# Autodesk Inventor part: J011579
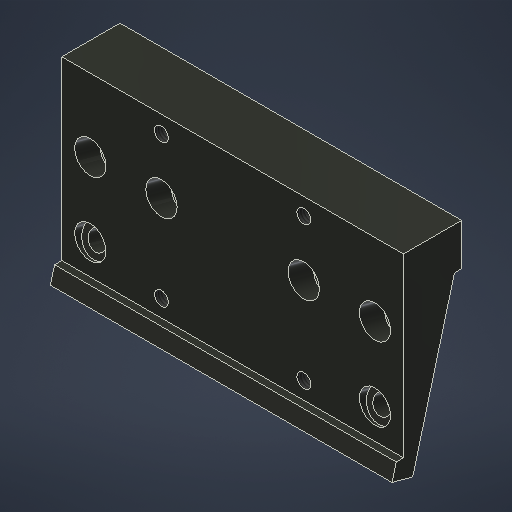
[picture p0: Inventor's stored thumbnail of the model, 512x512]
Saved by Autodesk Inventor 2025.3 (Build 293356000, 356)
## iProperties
RuleStatus: InUse
Created: 2026-02
Project: COMMON
Material: ALUMINUM, 6061-T651
Catalog Web Link: https://www.janelia.org/
Vendor: HHMI: JRC - JET
Document SubType Name: Modeling
Designer: sohna
Density: 2.7 g/cm^3
Appearance: RAL6015_Black_olive
Part Number: J011579
Description: VENT ROTATION TO GONIO BRKT
AfterDocSave0: file://Part Number Cleaner
LAB/DEPT: COMMON
REQUESTING SCIENTIST: COMMON
SURFACE ROUGHNESS: 63 Ra
DESIGN DEPARTMENT: HHMI: JRC - ID&F
SPECIAL FINISH: ANODIZE PER MIL-A-8625F, TYPE II, CLASS 2 (BLACK)
ALTERED ITEM PART NUMBER: N/A
ALTERED ITEM VENDOR: N/A
ALTERED ITEM DESCRIPTION: N/A
Title: Standard
Author: sohna
Revision Number: -
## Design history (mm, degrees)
sketch "Sketch1"
  geometry: L1 (0, 28.727)-(0, -62.166) reference; L2 (-106.448, 0)-(90.075, 0) reference; L3 (62, 0)-(0, 0); L4 (47.197, -17.904)-(-78.373, 15.742); L5 (47.197, -17.904)-(49.933, -49.181); L6 (-5.499, 4.013)-(-7.448, -3.262); L7 (-7.448, -3.262)-(47.197, -17.904); L8 (47.197, -17.904)-(47.419, -20.444); L9 (62, 0)-(62, -20.444); L10 (62, -20.444)-(47.419, -20.444); L11 (0, 0)-(0, 2.54); L12 (0, 2.54)-(-5.499, 4.013)
  constraints: 20 end point, 4 point on line, 2 perpendicular, 1 horizontal, 1 parallel, 1 vertical
  dimensions: "d0" = 17.90446 distance from line of L4.start L2; "d1" = 14.80312 horizontal distance of L4.start L3.start; "d2" = 62 distance from line of L1 L3.start; "d3" = 15 deg angle of L4 L3; "d4" = 110 deg angle of L5 L4; "d5" = 130 distance of L4.start L4.end; "d6" = 2.54 distance from line of L10 L4.start; "d7" = 2.54 distance from line of L2 L11.end; "d8" = 6.35 distance from line of L6 L3.end
extrude "Extrusion1" new body sketch "Sketch1" stored distance "d9" = 120; taper "d10" = 0 deg
sketch "Sketch2"
  geometry: L1 (60, 75.89)-(60, -21.338) reference; L2 (-24, 0)-(144, 0) reference; L3 (35, 56)-(85, 56); L4 (85, 56)-(85, 6); L5 (85, 6)-(35, 6); L6 (35, 6)-(35, 56); L7 (35, 56)-(85, 6); L8 (85, 56)-(35, 6); 6 further points
  constraints: 12 end point, 4 coincident, 2 midpoint, 2 parallel, 2 perpendicular, 1 horizontal, 1 point on line
  dimensions: "d11" = 50 distance of L3.end L4.end; "d12" = 31 distance from line of L2 point (60, 31)
hole "Hole1" sketch "Sketch2" at (35, 56), (35, 6), (85, 56), (85, 6) diameter "d13" = 4.917; stored, may be unused: countersink angle "d17" = 82 deg, drill point angle "d19" = 118 deg; dims "d14" = 11.9888, "d15" = 10.9982, "d16" = 19.05, "d18" = 17.0942
workplane "Work Plane1"
sketch "Sketch3"
  geometry: L1 (0, 71.813)-(120, 71.813) reference; L2 (60, 101.451)-(60, -1.325) reference; L3 (85, 56.813)-(35, 56.813); L4 (110, 31.813)-(10, 31.813); L5 (10, 31.813)-(10, 56.813); L6 (10, 56.813)-(110, 56.813); L7 (110, 56.813)-(110, 31.813); L8 (110, 31.813)-(10, 56.813); L9 (10, 31.813)-(110, 56.813); 10 further points
  constraints: 14 end point, 6 coincident, 4 midpoint, 2 parallel, 1 collinear, 1 horizontal, 1 perpendicular, 1 point on line, 1 symmetric about line
  dimensions: "d21" = 15 distance between parallel lines of L3 L1; "d29" = 50 distance of point (85, 56.813) point (35, 56.813); "d30" = 25 distance of L6.end L4.start; "d31" = 100 distance of L5.end L6.end
hole "Hole2" sketch "Sketch3" at (35, 56.813), (85, 56.813), (10, 31.813), (110, 31.813), (110, 56.813), (10, 56.813) diameter "d22" = 6.604; stored, may be unused: countersink angle "d26" = 82 deg, drill point angle "d28" = 118 deg; dims "d23" = 11.9888, "d24" = 10.9982, "d25" = 0, "d27" = 25.4
body "Solid1"
other parameters: "d32" = -5.08
